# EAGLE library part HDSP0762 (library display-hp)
LED DISPLAY 1-character dot matrix without decimal point
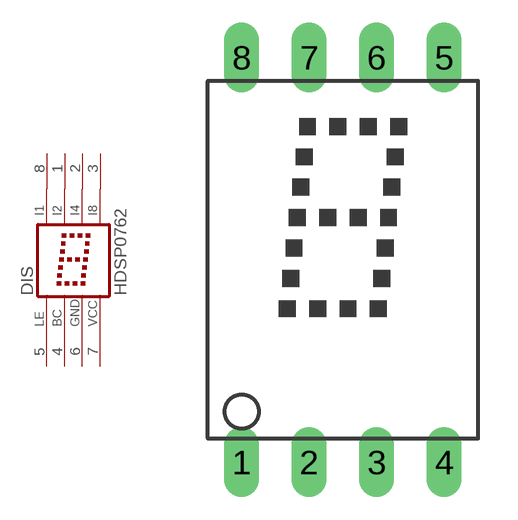
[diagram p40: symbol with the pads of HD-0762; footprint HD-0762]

Designator prefix DIS

## HDSP0762 (MF: AGILENT TECHNOLOGIES; MPN: HDSP-0762; OC_FARNELL: 9869883; OC_NEWARK: 39K9789)  [HD-0762]
1  I2  in
2  I4  in
3  I8  in
4  BC  in
5  LE  in
6  GND  pwr
7  VCC  pwr
8  I1  in

## Footprint HD-0762 (pad centres in mm)
LED DISPLAY 8-mm 1 character dot matrix without decimal point
drill 0.813 long: 1 -3.81,-7.62; 2 -1.27,-7.62; 3 1.27,-7.62; 4 3.81,-7.62; 5 3.81,7.62; 6 1.27,7.62; 7 -1.27,7.62; 8 -3.81,7.62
